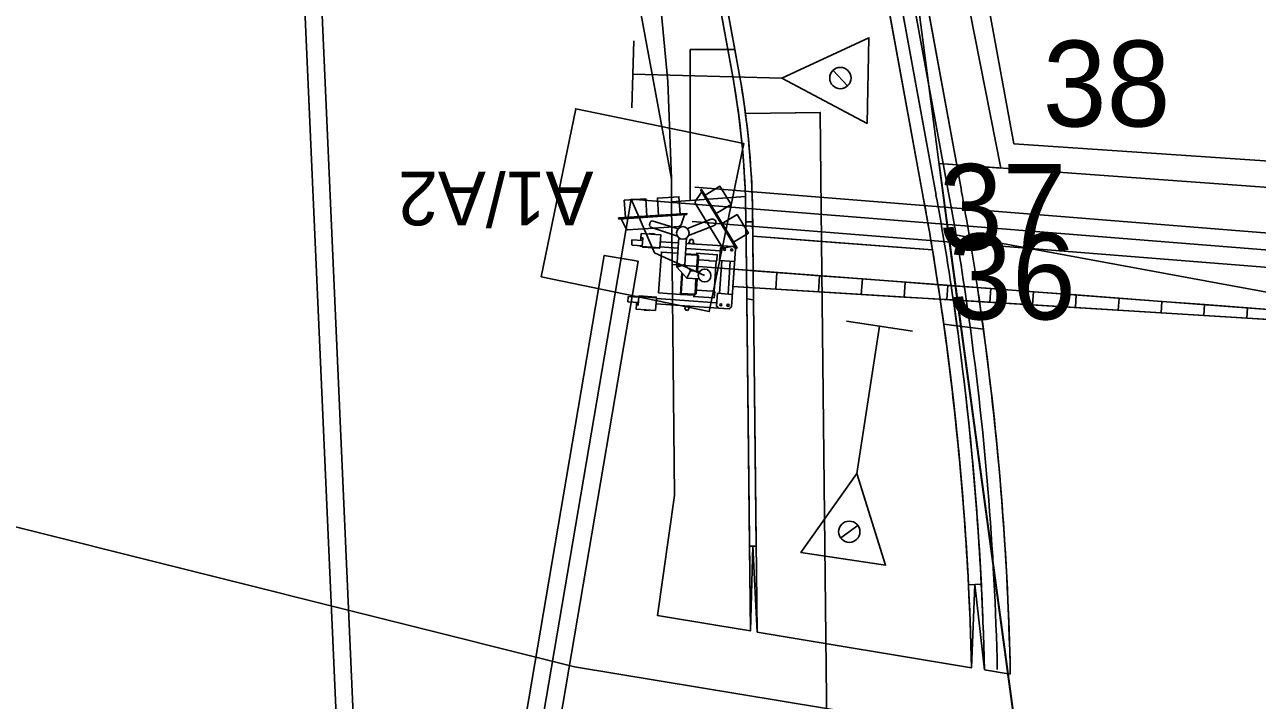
# Model space of a CAD drawing. Extents: x -728800 to -728100, y -1073200 to -1072700.
# Drawn here: x -728520.98 to -728506.62, y -1073041.72 to -1073033.85 of the extents above; entities that cross this region are included whole.
import ezdxf

# ---------------------------------------------------------------- set-up
doc = ezdxf.new("R2010")
doc.units = 0
for name, color, linetype in [('_NOR-návrh tenká', 7, 'Continuous'), ('_NOR-VDZ', 7, 'Continuous'), ('_NOR-šraf_+12', 7, 'Continuous'), ('_NOR-šraf_+6', 7, 'Continuous'), ('_NOR-šraf_chodník', 7, 'Continuous'), ('_NOR-šraf_signální pás', 7, 'Continuous'), ('_NOR-šraf_varovný pás', 7, 'Continuous'), ('_NOR-šraf_vozovka', 7, 'Continuous'), ('_NOR-šraf_zeleň', 7, 'Continuous'), ('A1_OBVOD Spravy železnic', 7, 'Continuous'), ('A2_OBVOD STAVBY', 7, 'Continuous'), ('B1_body_poloha', 7, 'Continuous'), ('B2_body_číslo', 7, 'Continuous'), ('B6_JŽM', 7, 'Continuous'), ('Default', 7, 'Continuous'), ('K_01_Hranice parcel', 7, 'Continuous'), ('KOS_kabelová trasa', 7, 'Continuous'), ('KOS_nové prvky PZZ', 7, 'Continuous'), ('KTA_PZZ rušené', 7, 'Continuous'), ('ZA_01_Trvalý_pro_SŽDC_dle_UMVZST', 7, 'Continuous'), ('ZA_02_Dočasný_do_1_roku', 7, 'Continuous')]:
    doc.layers.add(name, color=color, linetype=linetype)

# ---------------------------------------------------------------- blocks, each defined once
blk = doc.blocks.new('Závora A')
at = {"layer": 'Default'}
for p, q in [((0.395, 0.28), (0.046, 0.997)), ((-0.139, 0.725), (-0.935, 0.747)), ((-0.563, 0.613), (-0.27, 0.487)), ((0.138, 0.645), (-0.147, 0.563)), ((-0.697, 0.505), (-0.702, 0.477)), ((-0.596, 0.546), (-0.597, 0.54)), ((-0.535, 0.536), (-0.596, 0.546)), ((-0.268, 0.407), (-0.477, 0.44)), ((-0.277, 0.347), (-0.486, 0.381)), ((0.209, 0.268), (-0.188, 0.333)), ((0.244, 0.323), (-0.178, 0.392)), ((0.191, 0.16), (0.215, 0.304)), ((0.244, 0.323), (0.215, 0.304)), ((0.365, 0.304), (0.387, 0.276)), ((-0.313, 0.128), (-0.217, 0.151)), ((0.094, -0.192), (0.15, 0.154)), ((0.153, -0.224), (0.215, 0.156)), ((0.364, 0.132), (0.191, 0.16)), ((0.279, -0.392), (0.387, 0.276)), ((-0.292, -0.182), (-0.255, 0.051)), ((-0.207, -0.012), (-0.156, 0.07)), ((0.253, -0.24), (0.314, 0.14)), ((0.349, 0.041), (0.317, -0.157)), ((0.349, 0.041), (0.317, -0.157)), ((0.349, 0.041), (0.317, -0.157)), ((0.349, 0.041), (0.317, -0.157)), ((7.251, -1.126), (0.349, 0.041)), ((-0.822, -0.267), (-0.818, -0.239)), ((0.128, -0.392), (-0.593, -0.275)), ((0.112, -0.329), (-0.583, -0.216)), ((0.302, -0.248), (0.13, -0.22)), ((7.234, -1.232), (0.317, -0.157)), ((-0.739, -0.338), (-0.738, -0.331)), ((-0.679, -0.347), (-0.739, -0.338)), ((0.128, -0.392), (0.106, -0.365)), ((0.249, -0.412), (0.128, -0.392)), ((0.249, -0.412), (0.279, -0.392)), ((7.251, -1.126), (7.234, -1.232))]:
    blk.add_line(p, q, dxfattribs=at)
for points in [[(0.092, 0.931), (0.274, 1.02), (0.384, 0.794), (0.202, 0.706)], [(-0.856, 0.758), (-0.85, 0.96), (-0.599, 0.953), (-0.605, 0.751)], [(-0.217, 0.74), (-0.212, 0.942), (-0.463, 0.949), (-0.468, 0.747)], [(0.381, 0.307), (0.259, 0.299), (0.234, 0.31), (-0.029, 0.85), (-0.025, 0.875), (0.058, 0.972)], [(0.395, 0.28), (0.407, 0.286), (0.058, 1.002), (0.046, 0.997)], [(-0.139, 0.725), (-0.138, 0.738), (-0.935, 0.76), (-0.935, 0.747)], [(-0.169, 0.725), (-0.218, 0.613), (-0.24, 0.597), (-0.84, 0.613), (-0.86, 0.628), (-0.908, 0.746)], [(-0.549, 0.689), (-0.561, 0.687), (-0.575, 0.676), (-0.581, 0.66), (-0.584, 0.646), (-0.582, 0.633), (-0.575, 0.623), (-0.573, 0.62), (-0.569, 0.617), (-0.563, 0.613)], [(-0.549, 0.689), (-0.257, 0.571)], [(0.159, 0.566), (0.178, 0.576), (0.185, 0.588), (0.188, 0.603), (0.188, 0.619), (0.183, 0.629), (0.174, 0.636), (0.16, 0.643), (0.148, 0.644), (0.138, 0.645)], [(0.372, 0.357), (0.554, 0.446), (0.444, 0.671), (0.262, 0.583)], [(-0.804, 0.493), (-0.812, 0.44), (-0.807, 0.432), (-0.69, 0.413)], [(-0.804, 0.493), (-0.68, 0.473)], [(-0.465, 0.518), (-0.488, 0.371), (-0.691, 0.404), (-0.675, 0.502), (-0.697, 0.505), (-0.689, 0.555), (-0.465, 0.518)], [(-0.577, 0.536), (-0.536, 0.53)], [(-0.535, 0.536), (-0.536, 0.53)], [(-0.078, -0.033), (-0.207, -0.012), (-0.313, 0.128), (-0.258, 0.467)], [(-0.058, 0.054), (-0.156, 0.07), (-0.217, 0.151), (-0.168, 0.455)], [(-0.111, 0.433), (-0.124, 0.435), (-0.126, 0.428), (-0.13, 0.429), (-0.132, 0.42), (-0.136, 0.42), (-0.139, 0.397), (-0.148, 0.399), (-0.149, 0.393), (-0.15, 0.387)], [(0.159, 0.566), (-0.143, 0.48)], [(-0.111, 0.433), (-0.098, 0.431), (-0.098, 0.424), (-0.094, 0.423), (-0.095, 0.414), (-0.092, 0.413), (-0.095, 0.39), (-0.087, 0.389), (-0.088, 0.383), (-0.089, 0.377)], [(-0.691, 0.404), (-0.714, 0.408), (-0.712, 0.417)], [(-0.492, 0.372), (-0.493, 0.364), (-0.691, 0.396), (-0.69, 0.404)], [(-0.3, -0.193), (-0.552, -0.152), (-0.475, 0.319), (-0.287, 0.289)], [(0.244, 0.323), (0.365, 0.304)], [(-0.199, 0.263), (-0.072, 0.243), (-0.068, 0.24), (-0.065, 0.237), (-0.062, 0.232), (-0.061, 0.226), (-0.088, 0.059)], [(-0.197, 0.274), (-0.069, 0.253), (-0.059, 0.249), (-0.054, 0.243), (-0.049, 0.235), (-0.048, 0.231), (-0.076, 0.057)], [(-0.074, 0.268), (0.169, 0.228), (0.158, 0.16), (0.15, 0.154), (0.067, 0.167), (0.068, 0.17), (-0.048, 0.188), (-0.048, 0.192), (-0.054, 0.193)], [(-0.259, 0.057), (-0.3, -0.193)], [(0.349, 0.041), (0.317, -0.157), (0.811, -0.234), (0.842, -0.043), (0.349, 0.041)], [(-0.294, -0.193), (-0.292, -0.182), (-0.145, -0.206), (-0.14, -0.205), (-0.136, -0.203), (-0.132, -0.199), (-0.129, -0.194), (-0.103, -0.029)], [(-0.294, -0.193), (-0.145, -0.218), (-0.135, -0.217), (-0.128, -0.212), (-0.121, -0.207), (-0.118, -0.203), (-0.09, -0.031)], [(0.842, -0.043), (0.811, -0.234), (1.305, -0.31), (1.335, -0.126), (0.842, -0.043)], [(1.828, -0.209), (1.335, -0.126), (1.305, -0.31), (1.799, -0.387), (1.828, -0.209)], [(-0.92, -0.222), (-0.911, -0.169), (-0.904, -0.163), (-0.786, -0.182)], [(-0.92, -0.222), (-0.796, -0.242)], [(-0.606, -0.353), (-0.582, -0.206), (-0.785, -0.173), (-0.801, -0.271), (-0.822, -0.267), (-0.83, -0.316), (-0.606, -0.353)], [(-0.785, -0.173), (-0.807, -0.17), (-0.809, -0.179)], [(-0.586, -0.206), (-0.584, -0.198), (-0.782, -0.166), (-0.783, -0.173)], [(-0.155, -0.23), (0.089, -0.269), (0.1, -0.201), (0.094, -0.192), (0.011, -0.179), (0.011, -0.181), (-0.104, -0.163), (-0.106, -0.166), (-0.112, -0.165)], [(0.106, -0.365), (0.13, -0.22)], [(1.828, -0.209), (1.799, -0.387), (2.293, -0.464), (2.321, -0.293), (1.828, -0.209)], [(-0.718, -0.335), (-0.678, -0.341)], [(-0.679, -0.347), (-0.678, -0.341)], [(-0.243, -0.384), (-0.256, -0.381), (-0.256, -0.375), (-0.261, -0.374), (-0.259, -0.365), (-0.263, -0.364), (-0.259, -0.341), (-0.268, -0.34), (-0.267, -0.334), (-0.266, -0.328)], [(-0.243, -0.384), (-0.23, -0.386), (-0.228, -0.379), (-0.224, -0.38), (-0.222, -0.37), (-0.219, -0.371), (-0.215, -0.348), (-0.206, -0.35), (-0.206, -0.344), (-0.205, -0.338)], [(2.321, -0.293), (2.293, -0.464), (2.787, -0.541), (2.814, -0.376), (2.321, -0.293)], [(2.814, -0.376), (2.787, -0.541), (3.282, -0.618), (3.307, -0.459), (2.814, -0.376)], [(3.8, -0.543), (3.307, -0.459), (3.282, -0.618), (3.776, -0.694), (3.8, -0.543)], [(3.8, -0.543), (3.776, -0.694), (4.27, -0.771), (4.293, -0.626), (3.8, -0.543)], [(4.293, -0.626), (4.27, -0.771), (4.764, -0.848), (4.786, -0.709), (4.293, -0.626)], [(4.786, -0.709), (4.764, -0.848), (5.258, -0.925), (5.279, -0.793), (4.786, -0.709)], [(5.279, -0.793), (5.258, -0.925), (5.752, -1.001), (5.772, -0.876), (5.279, -0.793)], [(5.772, -0.876), (5.752, -1.001), (6.246, -1.078), (6.265, -0.959), (5.772, -0.876)], [(6.758, -1.043), (6.265, -0.959), (6.246, -1.078), (6.74, -1.155), (6.758, -1.043)], [(7.234, -1.232), (7.251, -1.126), (6.758, -1.043), (6.74, -1.155), (7.234, -1.232)]]:
    blk.add_lwpolyline(points, dxfattribs=at)
for centre, radius in [((-0.206, 0.518), 0.0735), ((0.261, 0.282), 0.0119), ((0.343, 0.268), 0.0119), ((0, 0), 0.0742), ((0.157, -0.358), 0.0119), ((0.24, -0.371), 0.0119)]:
    blk.add_circle(centre, radius, dxfattribs=at)

msp = doc.modelspace()

# ---------------------------------------------------------------- linework, layer by layer
at = {"layer": '_NOR-návrh tenká'}
for p, q in [((-728512.583, -1073034.881), (-728511.708, -1073034.871)), ((-728511.696, -1073036.371), (-728511.713, -1073034.871)), ((-728512.497, -1073036.311), (-728510.404, -1073036.468)), ((-728511.576, -1073047.173), (-728511.696, -1073036.371)), ((-728512.492, -1073036.713), (-728510.339, -1073036.874)), ((-728512.492, -1073036.713), (-728512.446, -1073040.922)), ((-728512.457, -1073039.922), (-728512.537, -1073039.923)), ((-728512.526, -1073040.909), (-728512.497, -1073039.923)), ((-728512.497, -1073039.923), (-728512.446, -1073040.922)), ((-728509.834, -1073040.364), (-728509.984, -1073040.371)), ((-728509.948, -1073041.338), (-728509.909, -1073040.368)), ((-728509.909, -1073040.368), (-728509.797, -1073041.363))]:
    msp.add_line(p, q, dxfattribs=at)
for points in [[(-728520.806, -1073029.105), (-728520.799, -1073028.805), (-728511.304, -1073029.031), (-728510.067, -1073035.777)], [(-728511.116, -1073032.553), (-728510.51, -1073035.858)], [(-728510.968, -1073032.525), (-728510.362, -1073035.831)], [(-728512.663, -1073034.374), (-728512.935, -1073032.886)], [(-728512.741, -1073034.388), (-728513.014, -1073032.9)], [(-728512.572, -1073036.707), (-728512.58, -1073036.067)], [(-728512.492, -1073036.713), (-728512.5, -1073036.066)], [(-728512.526, -1073040.909), (-728512.572, -1073036.707)], [(-728509.496, -1073041.413), (-728509.797, -1073041.363)]]:
    msp.add_lwpolyline(points, dxfattribs=at)
for centre, radius, start, end in [((-728522.499, -1073036.177), 9.92, 0.6348, 10.3872), ((-728522.499, -1073036.177), 10, 0.6348, 10.3872), ((-728544.789, -1073042.142), 34.85, 8.6933, 10.3872), ((-728544.789, -1073042.142), 35, 8.6367, 10.3872), ((-728544.789, -1073042.142), 35.3, 8.525, 10.3872), ((-728544.789, -1073042.142), 34.85, 1.3216, 8.6933), ((-728544.789, -1073042.142), 35, 1.2748, 8.6367), ((-728544.789, -1073042.142), 35.3, 1.1826, 8.525)]:
    msp.add_arc(centre, radius, start, end, dxfattribs=at)
at = {"layer": '_NOR-VDZ'}
msp.add_lwpolyline([(-728510.942, -1073031.839), (-728510.215, -1073035.804)], dxfattribs=at)
for start, end in [(8.1532, 10.3872), (1.2748, 8.1532)]:
    msp.add_arc((-728544.789, -1073042.142), 35.15, start, end, dxfattribs=at)
at = {"layer": '_NOR-šraf_+12'}
for p, q in [((-728511.116, -1073032.553), (-728510.51, -1073035.858)), ((-728510.362, -1073035.831), (-728510.968, -1073032.525)), ((-728510.339, -1073036.874), (-728510.186, -1073036.886)), ((-728510.339, -1073036.874), (-728510.186, -1073036.886)), ((-728510.118, -1073037.354), (-728510.272, -1073037.335)), ((-728510.272, -1073037.335), (-728510.118, -1073037.354))]:
    msp.add_line(p, q, dxfattribs=at)
msp.add_lwpolyline([(-728509.834, -1073040.364), (-728509.909, -1073040.368), (-728509.984, -1073040.371)], dxfattribs=at)
for radius, start, end in [(34.85, 8.6933, 10.3872), (35, 8.6367, 10.3872), (34.85, 8.3112, 8.6933), (35, 7.8617, 8.6367), (34.85, 7.9285, 8.3112), (34.85, 2.9119, 7.9285), (35, 2.9119, 7.8617)]:
    msp.add_arc((-728544.789, -1073042.142), radius, start, end, dxfattribs=at)
at = {"layer": '_NOR-šraf_+6'}
for p, q in [((-728512.707, -1073034.135), (-728512.935, -1073032.886)), ((-728513.014, -1073032.9), (-728512.788, -1073034.135)), ((-728512.788, -1073034.135), (-728512.707, -1073034.135)), ((-728512.572, -1073036.707), (-728512.579, -1073036.142)), ((-728512.579, -1073036.142), (-728512.499, -1073036.142)), ((-728512.499, -1073036.142), (-728512.497, -1073036.311)), ((-728512.497, -1073036.311), (-728512.492, -1073036.713)), ((-728512.492, -1073036.713), (-728512.572, -1073036.707)), ((-728512.569, -1073037.041), (-728512.572, -1073036.707)), ((-728512.489, -1073037.051), (-728512.569, -1073037.041)), ((-728512.569, -1073037.041), (-728512.489, -1073037.051))]:
    msp.add_line(p, q, dxfattribs=at)
for points in [[(-728512.663, -1073034.374), (-728512.707, -1073034.135), (-728512.788, -1073034.135), (-728512.741, -1073034.388)], [(-728512.58, -1073036.067), (-728512.579, -1073036.142), (-728512.499, -1073036.142), (-728512.5, -1073036.066)], [(-728512.572, -1073036.707), (-728512.492, -1073036.713), (-728512.489, -1073037.051)], [(-728512.489, -1073037.051), (-728512.457, -1073039.922), (-728512.497, -1073039.923), (-728512.537, -1073039.923), (-728512.569, -1073037.041)]]:
    msp.add_lwpolyline(points, dxfattribs=at)
for radius in [9.92, 10]:
    msp.add_arc((-728522.499, -1073036.177), radius, 0.6348, 10.3872, dxfattribs=at)
at = {"layer": '_NOR-šraf_chodník'}
for p, q in [((-728510.51, -1073035.858), (-728511.116, -1073032.553)), ((-728512.935, -1073032.886), (-728512.663, -1073034.374))]:
    msp.add_line(p, q, dxfattribs=at)
for points in [[(-728512.583, -1073034.881), (-728511.713, -1073034.871), (-728511.696, -1073036.371), (-728510.404, -1073036.468)], [(-728510.339, -1073036.874), (-728512.492, -1073036.713), (-728512.446, -1073040.922), (-728509.948, -1073041.338), (-728509.948, -1073041.338)]]:
    msp.add_lwpolyline(points, dxfattribs=at)
for centre, radius, start, end in [((-728522.499, -1073036.177), 10, 7.4438, 10.3872), ((-728544.789, -1073042.142), 34.85, 9.3691, 10.3872), ((-728544.789, -1073042.142), 34.85, 8.3112, 8.6933), ((-728544.789, -1073042.142), 34.85, 1.3216, 8.3112)]:
    msp.add_arc(centre, radius, start, end, dxfattribs=at)
at = {"layer": '_NOR-šraf_signální pás'}
msp.add_lwpolyline([(-728512.5, -1073036.066), (-728512.497, -1073036.311), (-728511.696, -1073036.371), (-728511.713, -1073034.871), (-728512.583, -1073034.881)], dxfattribs=at)
msp.add_arc((-728522.499, -1073036.177), 10, 0.6348, 7.4438, dxfattribs=at)
at = {"layer": '_NOR-šraf_varovný pás'}
for points in [[(-728510.404, -1073036.468), (-728511.696, -1073036.371), (-728512.497, -1073036.311), (-728512.492, -1073036.713)], [(-728512.492, -1073036.713), (-728510.339, -1073036.874)]]:
    msp.add_lwpolyline(points, dxfattribs=at)
msp.add_arc((-728544.789, -1073042.142), 34.85, 8.6933, 9.3691, dxfattribs=at)
at = {"layer": '_NOR-šraf_vozovka'}
for p, q in [((-728511.304, -1073029.031), (-728510.067, -1073035.777)), ((-728510.362, -1073035.831), (-728510.968, -1073032.525)), ((-728509.879, -1073036.909), (-728510.186, -1073036.886)), ((-728510.186, -1073036.886), (-728509.879, -1073036.909)), ((-728509.809, -1073037.394), (-728510.118, -1073037.354)), ((-728510.118, -1073037.354), (-728509.809, -1073037.394)), ((-728509.496, -1073041.413), (-728509.797, -1073041.363))]:
    msp.add_line(p, q, dxfattribs=at)
for radius, start, end in [(35, 8.6367, 10.3872), (35.3, 8.525, 10.3872), (35, 7.8617, 8.6367), (35.3, 7.73, 8.525), (35, 2.9119, 7.8617), (35.3, 1.1826, 7.73), (35, 1.2748, 2.9119)]:
    msp.add_arc((-728544.789, -1073042.142), radius, start, end, dxfattribs=at)
at = {"layer": '_NOR-šraf_zeleň'}
for p, q in [((-728513.489, -1073034.507), (-728513.751, -1073031.711)), ((-728513.489, -1073034.507), (-728513.751, -1073031.711)), ((-728513.014, -1073032.9), (-728512.788, -1073034.135)), ((-728513.919, -1073033.066), (-728513.447, -1073035.644)), ((-728512.788, -1073034.135), (-728513.228, -1073034.135)), ((-728513.228, -1073034.135), (-728513.228, -1073035.894)), ((-728512.788, -1073034.135), (-728513.228, -1073034.135)), ((-728513.228, -1073034.135), (-728513.228, -1073035.894)), ((-728512.741, -1073034.388), (-728512.788, -1073034.135)), ((-728513.447, -1073035.644), (-728513.489, -1073034.507)), ((-728513.447, -1073035.644), (-728513.489, -1073034.507)), ((-728513.444, -1073035.909), (-728513.447, -1073035.644)), ((-728513.228, -1073035.894), (-728513.444, -1073035.909)), ((-728513.228, -1073035.894), (-728512.584, -1073035.849))]:
    msp.add_line(p, q, dxfattribs=at)
for points in [[(-728512.584, -1073035.849), (-728513.444, -1073035.909), (-728513.437, -1073036.642)], [(-728513.437, -1073036.642), (-728512.572, -1073036.707), (-728512.58, -1073036.067)], [(-728512.928, -1073040.842), (-728512.526, -1073040.909), (-728512.537, -1073039.923), (-728512.572, -1073036.707), (-728513.437, -1073036.642), (-728513.41, -1073039.33), (-728513.61, -1073040.728), (-728512.928, -1073040.842)]]:
    msp.add_lwpolyline(points, dxfattribs=at)
for start, end in [(1.8949, 10.3872), (0.6348, 1.8949)]:
    msp.add_arc((-728522.499, -1073036.177), 9.92, start, end, dxfattribs=at)
at = {"layer": 'A1_OBVOD Spravy železnic'}
msp.add_lwpolyline([(-728604.14, -1072988.92), (-728582.13, -1073004.22), (-728556.03, -1073020.59), (-728543.86, -1073026.9), (-728510.71, -1073032.54), (-728510.22, -1073036.28), (-728509.42, -1073042.19), (-728509.9, -1073046.86), (-728541.12, -1073039.22), (-728572.55, -1073027.78), (-728581.66, -1073022.5), (-728594.83, -1073014.86), (-728598.74, -1073012.6)], dxfattribs=at)
at = {"layer": 'A2_OBVOD STAVBY'}
for points in [[(-728509.455, -1073035.234), (-728510.689, -1073028.502), (-728511.933, -1073022.707), (-728511.986, -1073020.002), (-728513.157, -1073020.217), (-728515.255, -1073019.379), (-728517.216, -1073018.59), (-728517.096, -1073019.442), (-728517.727, -1073020.685), (-728519.2, -1073021.56), (-728519.78, -1073021.597), (-728522.531, -1073023.408), (-728531.159, -1073023.437), (-728533.997, -1073023.341), (-728538.386, -1073022.967), (-728542.291, -1073022.287), (-728547.296, -1073020.586), (-728553.966, -1073017.86)], [(-728556.425, -1073019.431), (-728548.14, -1073022.833), (-728542.882, -1073024.621), (-728538.694, -1073025.349), (-728534.14, -1073025.737), (-728532.664, -1073025.787), (-728522.232, -1073025.806), (-728521.488, -1073028.32), (-728521.545, -1073030.726), (-728521.594, -1073032.788), (-728517.755, -1073032.879), (-728517.209, -1073045.129)], [(-728501.833, -1073035.753), (-728509.455, -1073035.234)]]:
    msp.add_lwpolyline(points, dxfattribs=at)
at = {"layer": 'B1_body_poloha'}
for p, q in [((-728510.33, -1073035.47), (-728510.33, -1073035.47)), ((-728509.61, -1073035.52), (-728509.61, -1073035.52)), ((-728510.22, -1073036.28), (-728510.22, -1073036.28))]:
    msp.add_line(p, q, dxfattribs=at)
at = {"layer": 'B6_JŽM'}
msp.add_lwpolyline([(-728300.809, -1073024.355), (-728320.8, -1073026.914), (-728374.008, -1073033.722), (-728429.095, -1073040.747), (-728461.932, -1073044.273), (-728481.199, -1073044.815), (-728499.353, -1073043.648), (-728506.01, -1073042.737), (-728514.574, -1073041.329), (-728535.848, -1073035.998), (-728561.353, -1073026.113), (-728583.963, -1073013.524), (-728603.757, -1072998.891), (-728619.185, -1072984.418), (-728634.193, -1072966.825), (-728646.078, -1072949.194), (-728656.182, -1072930.072), (-728664.987, -1072910.227), (-728668.627, -1072901.808), (-728681.252, -1072876.016), (-728691.886, -1072859.663)], dxfattribs=at)
at = {"layer": 'K_01_Hranice parcel'}
for points in [[(-728510.71, -1073032.54), (-728510.22, -1073036.28), (-728501.19, -1073037.94)], [(-728509.9, -1073046.86), (-728509.415, -1073042.185), (-728510.22, -1073036.28)]]:
    msp.add_lwpolyline(points, dxfattribs=at)
at = {"layer": 'KOS_kabelová trasa'}
for p, q in [((-728495.791, -1073037.133), (-728513.172, -1073035.74)), ((-728495.823, -1073037.531), (-728513.204, -1073036.139))]:
    msp.add_line(p, q, dxfattribs=at)
msp.add_lwpolyline([(-728514.965, -1073036.786), (-728514.562, -1073034.827), (-728512.603, -1073035.23), (-728513.006, -1073037.189)], close=True, dxfattribs=at)
for points in [[(-728513.395, -1073046.387), (-728515.647, -1073046.052), (-728513.917, -1073035.879)], [(-728513.917, -1073035.879), (-728513.644, -1073036.504), (-728513.06, -1073036.769)], [(-728495.185, -1073037.974), (-728495.156, -1073037.38), (-728513.916, -1073035.879)], [(-728515.318, -1073045.332), (-728515.712, -1073045.265), (-728514.228, -1073036.535), (-728513.834, -1073036.602), (-728515.318, -1073045.332)]]:
    msp.add_lwpolyline(points, dxfattribs=at)
at = {"layer": 'KTA_PZZ rušené'}
for p, q in [((-728513.886, -1073034.036), (-728513.908, -1073034.814)), ((-728511.56, -1073034.38), (-728511.393, -1073034.559)), ((-728510.637, -1073037.419), (-728511.405, -1073037.299)), ((-728511.273, -1073039.682), (-728511.472, -1073039.826))]:
    msp.add_line(p, q, dxfattribs=at)
for points in [[(-728513.897, -1073034.425), (-728512.159, -1073034.468), (-728511.144, -1073033.999), (-728511.166, -1073034.998), (-728512.159, -1073034.468)], [(-728511.021, -1073037.359), (-728511.284, -1073039.077), (-728510.949, -1073040.144), (-728511.936, -1073039.995), (-728511.284, -1073039.077)]]:
    msp.add_lwpolyline(points, dxfattribs=at)
for centre in [(-728511.477, -1073034.469), (-728511.477, -1073034.469), (-728511.373, -1073039.754), (-728511.373, -1073039.754)]:
    msp.add_circle(centre, 0.124, dxfattribs=at)
at = {"layer": 'ZA_01_Trvalý_pro_SŽDC_dle_UMVZST'}
msp.add_lwpolyline([(-728502.83, -1073049.48), (-728501.19, -1073037.94), (-728500.719, -1073036.161), (-728510.327, -1073035.465), (-728510.22, -1073036.28), (-728509.42, -1073042.19), (-728509.9, -1073046.86), (-728517.01, -1073045.12), (-728517.382, -1073047.311), (-728510.246, -1073048.375)], dxfattribs=at)
at = {"layer": 'ZA_02_Dočasný_do_1_roku'}
msp.add_lwpolyline([(-728531.162, -1073023.637), (-728526.817, -1073023.623), (-728522.471, -1073023.608), (-728519.714, -1073021.793), (-728519.139, -1073021.757), (-728517.575, -1073020.827), (-728516.889, -1073019.476), (-728516.969, -1073018.905), (-728513.177, -1073020.424), (-728512.181, -1073020.241), (-728512.132, -1073022.73), (-728509.606, -1073035.517), (-728510.327, -1073035.465), (-728509.415, -1073042.185), (-728509.9, -1073046.86), (-728517.01, -1073045.12), (-728517.286, -1073038.902), (-728517.563, -1073032.683), (-728521.389, -1073032.592), (-728521.287, -1073028.294), (-728522.083, -1073025.607), (-728532.66, -1073025.587)], dxfattribs=at)

# ---------------------------------------------------------------- block references
at = {"layer": 'KOS_nové prvky PZZ', "rotation": 5.302731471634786}
msp.add_blockref('Závora A', (-728513.06, -1073036.769), dxfattribs=at)

# ---------------------------------------------------------------- texts
at = {"layer": 'B2_body_číslo'}
for s, p in [('38', (-728509.118, -1073035.033)), ('37', (-728510.33, -1073036.47)), ('36', (-728510.22, -1073037.28))]:
    msp.add_text(s, height=1, dxfattribs=at).set_placement(p)
at = {"layer": 'KOS_nové prvky PZZ'}
msp.add_text('A1/A2', height=0.625, rotation=180, dxfattribs=at).set_placement((-728514.355, -1073035.559))

doc.saveas('drawing.dxf')
